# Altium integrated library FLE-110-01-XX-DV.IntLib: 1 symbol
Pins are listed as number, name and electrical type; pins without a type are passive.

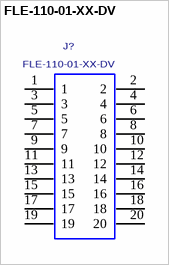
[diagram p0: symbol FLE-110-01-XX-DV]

## FLE-110-01-XX-DV
designator J?
DUAL ROW 0.050'' STRIP ASSEMBLY.; MANUFACTURER: SAMTEC
footprint FLE-110-01-XX-DV
pins: 1, 2, 3, 4, 5, 6, 7, 8, 9, 10, 11, 12, 13, 14, 15, 16, 17, 18, 19, 20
